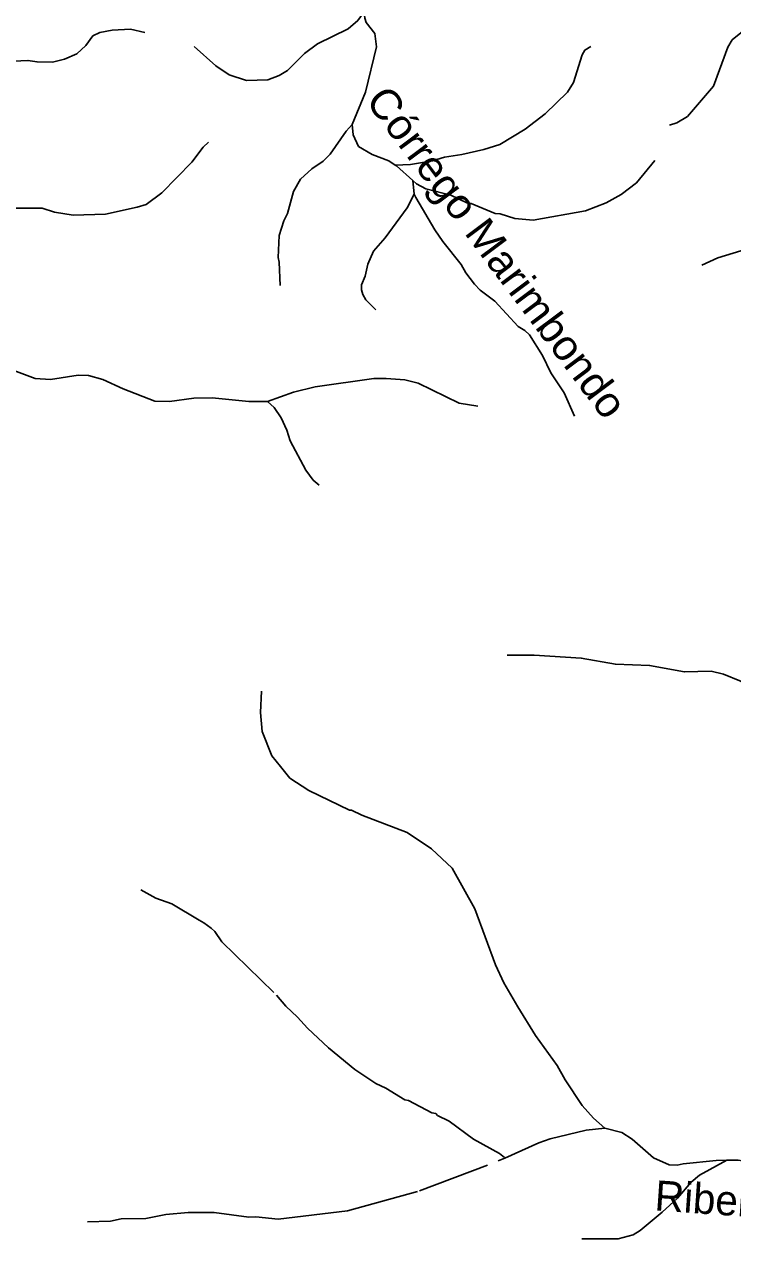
# Model space of a CAD drawing. Extents: x 393 to 446.6, y 8175.5 to 8231.
# Drawn here: x 400.44 to 404.19, y 8175.56 to 8182.01 of the extents above; entities that cross this region are included whole.
import ezdxf
from ezdxf.enums import TextEntityAlignment as Align

# ---------------------------------------------------------------- set-up
doc = ezdxf.new("R2010")
doc.units = 0
doc.header["$LTSCALE"] = 0.064
doc.linetypes.add('LONG_DASHED', pattern=[7.5, 6, -1.5])
doc.layers.add('61', color=7, linetype='Continuous')
doc.layers.add('7', color=7, linetype='Continuous', lineweight=25)
doc.layers.add('9', color=7, linetype='LONG_DASHED', lineweight=25)

msp = doc.modelspace()

# ---------------------------------------------------------------- linework, layer by layer
at = {"layer": '7'}
msp.add_line((402.4998, 8181.1162), (402.4928, 8181.1872), dxfattribs=at)
for points in [[(401.3352, 8181.8967), (401.4498, 8181.7946), (401.5208, 8181.7477), (401.6113, 8181.717), (401.7243, 8181.7203), (401.7857, 8181.7445), (401.8293, 8181.7703), (401.9197, 8181.8608), (401.9875, 8181.9108), (402.1506, 8181.9916), (402.2007, 8182.0351), (402.2355, 8182.0803)], [(402.1717, 8181.4837), (402.2426, 8181.6557), (402.3007, 8181.8947), (402.2911, 8181.9657), (402.2459, 8182.0239), (402.2378, 8182.0478), (402.2355, 8182.0803)], [(401.0729, 8181.9717), (400.9977, 8181.9883), (400.9008, 8181.9835), (400.8362, 8181.9722), (400.799, 8181.9544), (400.7619, 8181.9028), (400.7134, 8181.8591), (400.6489, 8181.8301), (400.5843, 8181.8139), (400.5035, 8181.8155), (400.4551, 8181.8236), (400.3808, 8181.8204), (400.2355, 8181.8349), (400.1386, 8181.8349), (400.0159, 8181.8511), (399.9803, 8181.8624), (399.9367, 8181.893), (399.8902, 8181.9581)], [(403.4343, 8181.8971), (403.4028, 8181.8785), (403.3891, 8181.8527), (403.3423, 8181.7074), (403.3116, 8181.6557), (403.1938, 8181.541), (403.0872, 8181.4587), (402.9532, 8181.3779), (402.8676, 8181.3521), (402.7513, 8181.3246), (402.6609, 8181.3117), (402.5963, 8181.2923), (402.48, 8181.273), (402.3998, 8181.2697)], [(401.7907, 8180.6317), (401.7856, 8180.7547), (401.7792, 8180.7805), (401.7856, 8180.8968), (401.8099, 8180.9743), (401.8292, 8181.013), (401.8615, 8181.1293), (401.8987, 8181.1939), (401.9584, 8181.2488), (402.0182, 8181.2907), (402.0553, 8181.3279), (402.1393, 8181.449), (402.1717, 8181.4837)], [(402.3998, 8181.2697), (402.3654, 8181.2923), (402.2766, 8181.3246), (402.2055, 8181.3682), (402.1764, 8181.4296), (402.1717, 8181.4837)], [(401.41, 8181.3914), (401.3819, 8181.3634), (401.3222, 8181.2843), (401.1639, 8181.1228), (401.08, 8181.0614), (401.0332, 8181.0469), (400.8652, 8181.0098), (400.6941, 8181.0049), (400.5956, 8181.0195), (400.5294, 8181.0404), (400.3065, 8181.0404), (400.2032, 8181.0517), (400.1773, 8181.063), (400.1305, 8181.0663), (400.1255, 8181.0667)], [(402.4928, 8181.1872), (402.4067, 8181.2652), (402.3998, 8181.2697)], [(403.7739, 8181.2928), (403.6766, 8181.1745), (403.5958, 8181.1131), (403.5167, 8181.0695), (403.4069, 8181.0275), (403.1292, 8180.9775), (403.0323, 8180.9872), (402.9548, 8181.0114), (402.9289, 8181.013), (402.8014, 8181.0663), (402.7788, 8181.0695), (402.6936, 8181.1098), (402.5608, 8181.1438), (402.5123, 8181.1696), (402.4928, 8181.1872)], [(402.297, 8180.5034), (402.2442, 8180.556), (402.2281, 8180.5835), (402.2216, 8180.6093), (402.22, 8180.6352), (402.241, 8180.6804), (402.2539, 8180.745), (402.2846, 8180.8128), (402.346, 8180.8838), (402.4622, 8181.0421), (402.4998, 8181.1162)], [(403.3486, 8179.9401), (403.2938, 8180.0635), (403.2228, 8180.1701), (403.1792, 8180.2605), (403.1098, 8180.3703), (403.0855, 8180.3929), (403.05, 8180.4139), (402.9273, 8180.5496), (402.8498, 8180.6077), (402.8191, 8180.6384), (402.7723, 8180.6981), (402.7481, 8180.7433), (402.6512, 8180.8644), (402.6092, 8180.9258), (402.5091, 8181.097), (402.4998, 8181.1162)], [(401.724, 8180.0176), (401.6242, 8180.0183), (401.4304, 8180.0377), (401.3335, 8180.0344), (401.2043, 8180.0183), (401.1268, 8180.0199), (400.9589, 8180.0845), (400.8507, 8180.1345), (400.7748, 8180.1555), (400.7199, 8180.1572), (400.5746, 8180.1345), (400.4938, 8180.1394), (400.3808, 8180.1814), (400.3501, 8180.2072), (400.3123, 8180.271)], [(402.8374, 8179.992), (402.7384, 8180.0086), (402.5204, 8180.1152), (402.451, 8180.1313), (402.3509, 8180.1394), (402.2863, 8180.1394), (401.9762, 8180.0958), (401.86, 8180.0667), (401.724, 8180.0176)], [(401.9962, 8179.5748), (401.9649, 8179.6001), (401.9261, 8179.6534), (401.8438, 8179.81), (401.826, 8179.8665), (401.7953, 8179.9311), (401.7582, 8179.986), (401.724, 8180.0176)], [(402.9926, 8178.6749), (403.1356, 8178.6748), (403.3843, 8178.6586), (403.5652, 8178.6263), (403.746, 8178.6199), (403.9301, 8178.5859), (404.0722, 8178.5892), (404.1368, 8178.573), (404.224, 8178.5391), (404.3887, 8178.4535), (404.5308, 8178.4051), (404.5986, 8178.3744), (404.6891, 8178.3292), (404.8505, 8178.2226), (405.0153, 8178.129), (405.0411, 8178.108), (405.1961, 8178.0434), (405.2914, 8178.0224), (405.3175, 8178.0129)]]:
    msp.add_lwpolyline(points, dxfattribs=at)
at = {"layer": '9'}
for points in [[(403.8521, 8181.4808), (403.8895, 8181.4925), (403.9463, 8181.5265), (404.0851, 8181.688), (404.1594, 8181.893), (404.1836, 8181.9318), (404.2466, 8181.9835), (404.3064, 8182.0029), (404.3758, 8181.9932), (404.4307, 8181.9641), (404.4614, 8181.9544), (404.5533, 8181.8914)], [(404.0222, 8180.7397), (404.1074, 8180.7782), (404.3467, 8180.8515), (404.421, 8180.8886), (404.4469, 8180.8935), (404.589, 8180.9565), (404.7763, 8181.0614), (404.8058, 8181.0819)], [(401.6912, 8178.4833), (401.6865, 8178.3702), (401.6952, 8178.2695), (401.7469, 8178.1419), (401.7922, 8178.0841), (401.8406, 8178.0224), (401.9423, 8177.9578), (402.1571, 8177.8528), (402.1684, 8177.8528), (402.2217, 8177.827), (402.4623, 8177.735), (402.5914, 8177.6494), (402.7012, 8177.546), (402.8207, 8177.3313), (402.9305, 8177.0342), (402.9742, 8176.9389), (403.0484, 8176.8113), (403.1421, 8176.6595), (403.2567, 8176.5013), (403.2987, 8176.4254), (403.3891, 8176.2897), (403.4489, 8176.2219), (403.5094, 8176.17)], [(401.0532, 8177.4318), (401.1317, 8177.3878), (401.2173, 8177.3571), (401.3615, 8177.2711), (401.3852, 8177.257), (401.424, 8177.2279), (401.4449, 8177.2102), (401.4821, 8177.1569), (401.7711, 8176.8743), (401.8196, 8176.8162), (401.8825, 8176.758), (401.9342, 8176.6999), (402.0456, 8176.5949), (402.1861, 8176.4803), (402.2975, 8176.406), (402.3492, 8176.3818), (402.451, 8176.3188), (402.4703, 8176.3156), (402.5931, 8176.251), (402.614, 8176.2477), (402.6237, 8176.2364), (402.6851, 8176.2058), (402.8143, 8176.1121), (402.9516, 8176.0346), (402.9772, 8176.0139), (402.9801, 8176.0116)], [(402.9801, 8176.0116), (403.1598, 8176.0927), (403.2196, 8176.1137), (403.4096, 8176.1596), (403.5094, 8176.17)], [(403.5094, 8176.17), (403.5991, 8176.146), (403.6539, 8176.1121), (403.767, 8176.012), (403.8494, 8175.9748), (403.8914, 8175.9732), (403.9237, 8175.9813), (404.0981, 8175.999), (404.1544, 8175.9993)], [(400.7707, 8175.6728), (400.8911, 8175.6777), (400.9476, 8175.689), (401.0784, 8175.6906), (401.185, 8175.7132), (401.3028, 8175.723), (401.4401, 8175.7229), (401.6242, 8175.6987), (401.6613, 8175.7004), (401.7792, 8175.6874), (402.1474, 8175.731), (402.5285, 8175.8376), (402.9451, 8175.9958), (402.9801, 8176.0116)], [(403.3875, 8175.5843), (403.5797, 8175.5841), (403.6588, 8175.6051), (403.696, 8175.6276), (403.8122, 8175.7245), (403.893, 8175.7988), (403.9656, 8175.8844), (404.0108, 8175.9215), (404.1544, 8175.9993)], [(404.1544, 8175.9993), (404.2142, 8175.9996), (404.2831, 8175.9891), (404.3693, 8175.9538), (404.4194, 8175.9216), (404.4824, 8175.8941), (404.5938, 8175.8537), (404.6891, 8175.8553), (404.8344, 8175.8941), (404.9264, 8175.8974), (405.3737, 8175.8521), (405.4964, 8175.8586), (405.6806, 8175.844), (405.7562, 8175.8041)]]:
    msp.add_lwpolyline(points, dxfattribs=at)

# ---------------------------------------------------------------- texts
at = {"layer": '61', "width": 1.05}
msp.add_text('Córrego Marimbondo', height=0.16, rotation=306.845, dxfattribs=at).set_placement((402.8736, 8180.7604), align=Align.CENTER)
at = {"layer": '61'}
msp.add_text('Ribeirão Água Limpa', height=0.16, rotation=356.078, dxfattribs=at).set_placement((404.7662, 8175.666), align=Align.CENTER)

doc.saveas('drawing.dxf')
